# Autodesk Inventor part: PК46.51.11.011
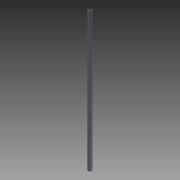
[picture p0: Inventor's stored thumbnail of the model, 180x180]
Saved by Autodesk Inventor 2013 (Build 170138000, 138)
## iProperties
Shininess: 64.0
Length Units: 11269
Angle Units: 11279
Time Units: 11290
Mass Units: 11283
Length Display Precision: 3
Angle Display Precision: 2
Compacted: True
Part Number: PК46.51.11.011
Document SubType Name: Modeling
Created: 2004-07
Material: Steel, Mild
Designer: =<Author>
Manufacturer: Standard
Standards Organization: Custom
Description: pipe
Density: 7.86 g/cm^3
Mass: 2430.67 g
Surface Area: 3097.06 cm^2
Volume: 309.245 cm^3
Density: 0.0
Volumn: 0.0
Area: 0.0
PropertySet Name: Model Information
Control State: 0
Master: False
Checked Out: False
Checked Out Date: 2008-10-15
Last Check In Date: 2008-10-15
Author: PVitaliy
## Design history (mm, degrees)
sketch "Эскиз1"
  geometry: L1 (4, 0)-(26, 0); L2 (30, 4)-(30, 26); L3 (26, 30)-(4, 30); L4 (0, 26)-(0, 4); L5 (2, 26)-(2, 4); L6 (4, 2)-(26, 2); L7 (28, 4)-(28, 26); L8 (26, 28)-(4, 28); A1 r 4 centre (4, 26) between (4, 30) and (0, 26); A2 r 4 centre (26, 26) between (30, 26) and (26, 30); A3 r 4 centre (26, 4) between (26, 0) and (30, 4); A4 r 4 centre (4, 4) between (0, 4) and (4, 0); A5 r 2 centre (4, 26) between (4, 28) and (2, 26); A6 r 2 centre (4, 4) between (2, 4) and (4, 2); A7 r 2 centre (26, 4) between (26, 2) and (28, 4); A8 r 2 centre (26, 26) between (28, 26) and (26, 28); 3 further points
  constraints: 16 end point, 16 point on circle, 8 centre point, 8 tangent, 6 point on line, 4 parallel, 2 equal radius, 2 perpendicular, 1 horizontal, 8 other
  dimensions: "d0" = 30 distance of point (0, 30) point (0, 0); "d1" = 30 distance of point (0, 0) point (30, 0); "d2" = 4 radius of A1; "d3" = 4 radius of A2; "d4" = 2 distance between parallel lines of L1 L6
extrude "Выдавливание1" new body sketch "Эскиз1" distance "d5" = 1450; taper "d6" = 0 deg
sketch "Эскиз2"
  geometry: L1 (0, 1450)-(-22, 1450) reference; L2 (-26, 1450)-(-26, 0) reference; L3 (-26, 1450)-(-22, 1450) reference; L4 (-16, 1450)-(-26, 1440)
  constraints: 2 end point, 2 point on line
  dimensions: "d7" = 10 horizontal distance of L4.start L4.end; "d8" = 10 horizontal distance of L4.start L4.end
extrude "Выдавливание2" cut sketch "Эскиз2" stored distance "d9" = 10; taper "d10" = 0 deg
body "Solid1"
